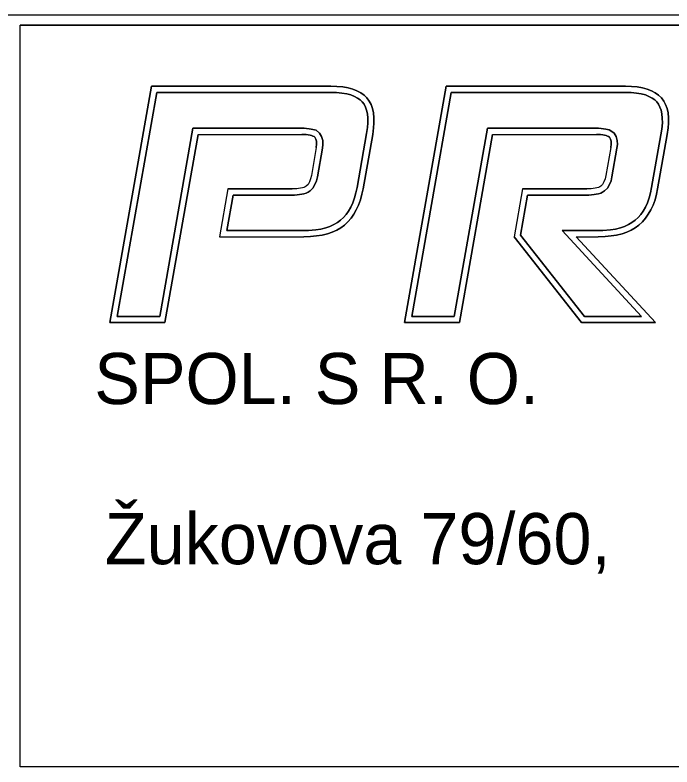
# Model space of a CAD drawing. Extents: x 448 to 763, y 27 to 171.
# Drawn here: x 731.72 to 743.92, y 48.52 to 62.49 of the extents above; entities that cross this region are included whole.
import ezdxf

# ---------------------------------------------------------------- set-up
doc = ezdxf.new("R2010")
doc.units = 0
doc.layers.add('000_rozpiska', color=7, linetype='Continuous')

msp = doc.modelspace()

# ---------------------------------------------------------------- linework, layer by layer
at = {"layer": '000_rozpiska'}
for p, q in [((758.888, 62.487), (672.438, 62.487)), ((758.888, 62.487), (672.438, 62.487)), ((758.888, 62.297), (731.813, 62.297)), ((731.813, 48.521), (731.813, 62.297)), ((733.48, 56.774), (734.254, 61.165)), ((734.253, 61.165), (737.585, 61.165)), ((738.951, 56.774), (739.725, 61.165)), ((739.724, 61.165), (743.056, 61.165)), ((735.118, 60.27), (734.502, 56.774)), ((735.118, 60.27), (737.047, 60.27)), ((738.361, 60.27), (738.183, 59.257)), ((740.589, 60.27), (739.973, 56.774)), ((740.589, 60.27), (742.518, 60.27)), ((743.832, 60.27), (743.654, 59.257)), ((737.314, 60.027), (737.222, 59.507)), ((742.785, 60.027), (742.693, 59.507)), ((735.672, 59.257), (735.516, 58.37)), ((735.672, 59.257), (736.868, 59.257)), ((741.143, 59.257), (740.987, 58.37)), ((741.143, 59.257), (742.339, 59.257)), ((735.516, 58.37), (737.081, 58.37)), ((742.239, 56.774), (740.987, 58.37)), ((742.14, 58.37), (742.551, 58.37)), ((743.615, 56.774), (742.14, 58.37)), ((734.502, 56.774), (733.48, 56.774)), ((739.973, 56.774), (738.951, 56.774)), ((743.615, 56.774), (742.239, 56.774)), ((760.123, 48.521), (731.813, 48.521))]:
    msp.add_line(p, q, dxfattribs=at)
for points in [[(731.813, 48.521), (731.813, 62.297), (758.888, 62.297)], [(760.123, 61.062), (760.123, 48.521), (731.813, 48.521)], [(737.991, 61.111), (737.903, 61.135), (737.804, 61.152), (737.697, 61.162), (737.585, 61.165), (734.254, 61.165), (733.48, 56.774), (734.502, 56.774), (735.118, 60.27), (737.047, 60.27), (737.082, 60.269), (737.124, 60.267), (737.163, 60.263), (737.197, 60.257), (737.226, 60.25), (737.251, 60.24), (737.271, 60.229), (737.287, 60.216), (737.308, 60.184), (737.319, 60.142), (737.32, 60.087), (737.314, 60.027), (737.222, 59.507), (737.207, 59.444), (737.186, 59.387), (737.16, 59.342), (737.127, 59.309), (737.107, 59.297), (737.084, 59.286), (737.055, 59.277), (737.023, 59.269), (736.986, 59.264), (736.949, 59.26), (736.904, 59.258), (736.868, 59.257), (735.672, 59.257), (735.516, 58.37), (737.081, 58.37), (737.207, 58.373), (737.32, 58.384), (737.421, 58.4), (737.524, 58.426), (737.609, 58.455), (737.694, 58.494), (737.768, 58.537), (737.836, 58.587), (737.902, 58.645), (737.959, 58.712), (738.01, 58.786), (738.057, 58.867), (738.098, 58.957), (738.134, 59.057), (738.162, 59.16), (738.183, 59.257), (738.361, 60.27), (738.378, 60.389), (738.385, 60.481), (738.383, 60.58), (738.376, 60.669), (738.357, 60.751), (738.331, 60.823), (738.297, 60.89), (738.253, 60.948), (738.201, 60.999), (738.14, 61.043), (738.069, 61.08), (737.991, 61.111)], [(734.349, 61.051), (737.581, 61.051), (737.69, 61.048), (737.789, 61.039), (737.878, 61.023), (737.956, 61.002), (738.022, 60.976), (738.08, 60.946), (738.128, 60.911), (738.167, 60.873), (738.2, 60.829), (738.226, 60.778), (738.247, 60.72), (738.263, 60.651), (738.269, 60.574), (738.271, 60.484), (738.265, 60.401), (738.249, 60.288), (738.071, 59.281), (738.051, 59.187), (738.025, 59.092), (737.992, 59), (737.955, 58.92), (737.914, 58.847), (737.868, 58.782), (737.82, 58.725), (737.764, 58.675), (737.706, 58.633), (737.642, 58.595), (737.566, 58.561), (737.492, 58.535), (737.398, 58.512), (737.305, 58.497), (737.168, 58.484), (735.652, 58.484), (735.768, 59.143), (736.87, 59.143), (736.907, 59.144), (736.957, 59.146), (737.001, 59.151), (737.044, 59.157), (737.085, 59.167), (737.126, 59.18), (737.161, 59.196), (737.199, 59.219), (737.251, 59.272), (737.289, 59.337), (737.317, 59.41), (737.334, 59.484), (737.427, 60.014), (737.435, 60.083), (737.432, 60.158), (737.413, 60.231), (737.373, 60.293), (737.309, 60.346), (737.22, 60.369), (737.179, 60.376), (737.133, 60.381), (737.086, 60.383), (737.05, 60.384), (735.022, 60.384), (734.406, 56.888), (733.616, 56.888), (734.349, 61.051)], [(738.263, 60.651), (738.247, 60.72), (738.226, 60.778), (738.2, 60.829), (738.167, 60.873), (738.128, 60.911), (738.08, 60.946), (738.022, 60.976), (737.956, 61.002), (737.878, 61.023), (737.789, 61.039), (737.69, 61.048), (737.581, 61.051), (734.349, 61.051), (733.616, 56.888), (734.406, 56.888), (735.022, 60.384), (737.05, 60.384), (737.086, 60.383), (737.133, 60.381), (737.179, 60.376), (737.22, 60.369), (737.309, 60.346), (737.373, 60.293), (737.413, 60.231), (737.432, 60.158), (737.435, 60.083), (737.427, 60.014), (737.334, 59.484), (737.317, 59.41), (737.289, 59.337), (737.251, 59.272), (737.199, 59.219), (737.161, 59.196), (737.126, 59.18), (737.085, 59.167), (737.044, 59.157), (737.001, 59.151), (736.957, 59.146), (736.907, 59.144), (736.87, 59.143), (735.768, 59.143), (735.652, 58.484), (737.168, 58.484), (737.305, 58.497), (737.398, 58.512), (737.492, 58.535), (737.566, 58.561), (737.642, 58.595), (737.706, 58.633), (737.764, 58.675), (737.82, 58.725), (737.868, 58.782), (737.914, 58.847), (737.955, 58.92), (737.992, 59), (738.025, 59.092), (738.051, 59.187), (738.071, 59.281), (738.249, 60.288), (738.265, 60.401), (738.271, 60.484), (738.269, 60.574), (738.263, 60.651)], [(735.022, 60.384), (734.406, 56.888), (733.616, 56.888), (734.349, 61.051), (737.581, 61.051), (737.69, 61.048), (737.789, 61.039), (737.878, 61.023), (737.956, 61.002), (738.022, 60.976), (738.08, 60.946), (738.128, 60.911), (738.167, 60.873), (738.2, 60.829), (738.226, 60.778), (738.247, 60.72), (738.263, 60.651), (738.269, 60.574), (738.271, 60.484), (738.265, 60.401), (738.249, 60.288), (738.071, 59.281), (738.051, 59.187), (738.025, 59.092), (737.992, 59), (737.955, 58.92), (737.914, 58.847), (737.868, 58.782), (737.82, 58.725), (737.764, 58.675), (737.706, 58.633), (737.642, 58.595), (737.566, 58.561), (737.492, 58.535), (737.398, 58.512), (737.305, 58.497), (737.168, 58.484), (735.652, 58.484), (735.768, 59.143), (736.87, 59.143), (736.907, 59.144), (736.957, 59.146), (737.001, 59.151), (737.044, 59.157), (737.085, 59.167), (737.126, 59.18), (737.161, 59.196), (737.199, 59.219), (737.251, 59.272), (737.289, 59.337), (737.317, 59.41), (737.334, 59.484), (737.427, 60.014), (737.435, 60.083), (737.432, 60.158), (737.413, 60.231), (737.373, 60.293), (737.309, 60.346), (737.22, 60.369), (737.179, 60.376), (737.133, 60.381), (737.086, 60.383), (737.05, 60.384), (735.022, 60.384)], [(737.585, 61.165), (737.697, 61.162), (737.804, 61.152), (737.903, 61.135), (737.991, 61.111), (738.069, 61.08), (738.14, 61.043), (738.201, 60.999), (738.253, 60.948), (738.297, 60.89), (738.331, 60.823), (738.357, 60.751), (738.376, 60.669), (738.383, 60.58), (738.385, 60.481), (738.378, 60.389), (738.361, 60.27)], [(743.849, 60.389), (743.856, 60.481), (743.854, 60.58), (743.847, 60.669), (743.828, 60.751), (743.802, 60.823), (743.768, 60.89), (743.724, 60.948), (743.672, 60.999), (743.611, 61.043), (743.54, 61.08), (743.462, 61.111), (743.374, 61.135), (743.275, 61.152), (743.168, 61.162), (743.056, 61.165), (739.725, 61.165), (738.951, 56.774), (739.973, 56.774), (740.589, 60.27), (742.518, 60.27), (742.553, 60.269), (742.595, 60.267), (742.634, 60.263), (742.668, 60.257), (742.697, 60.25), (742.722, 60.24), (742.742, 60.229), (742.758, 60.216), (742.779, 60.184), (742.79, 60.142), (742.791, 60.087), (742.785, 60.027), (742.693, 59.507), (742.678, 59.444), (742.657, 59.387), (742.631, 59.342), (742.598, 59.309), (742.578, 59.297), (742.555, 59.286), (742.526, 59.277), (742.494, 59.269), (742.457, 59.264), (742.42, 59.26), (742.375, 59.258), (742.339, 59.257), (741.143, 59.257), (740.987, 58.37), (742.239, 56.774), (743.615, 56.774), (742.14, 58.37), (742.551, 58.37), (742.678, 58.373), (742.791, 58.384), (742.892, 58.4), (742.995, 58.426), (743.08, 58.455), (743.165, 58.494), (743.239, 58.537), (743.307, 58.587), (743.373, 58.645), (743.43, 58.712), (743.481, 58.786), (743.528, 58.867), (743.569, 58.957), (743.605, 59.057), (743.633, 59.16), (743.654, 59.257), (743.832, 60.27), (743.849, 60.389)], [(740.493, 60.384), (739.877, 56.888), (739.087, 56.888), (739.82, 61.051), (743.052, 61.051), (743.161, 61.048), (743.26, 61.039), (743.349, 61.023), (743.426, 61.002), (743.493, 60.976), (743.551, 60.946), (743.599, 60.911), (743.638, 60.873), (743.671, 60.829), (743.697, 60.778), (743.718, 60.72), (743.734, 60.651), (743.74, 60.574), (743.742, 60.484), (743.733, 60.365), (743.542, 59.281), (743.522, 59.187), (743.496, 59.092), (743.463, 59), (743.426, 58.92), (743.385, 58.847), (743.339, 58.782), (743.291, 58.725), (743.235, 58.675), (743.177, 58.633), (743.113, 58.595), (743.037, 58.561), (742.963, 58.535), (742.869, 58.512), (742.776, 58.497), (742.639, 58.484), (741.88, 58.484), (743.355, 56.888), (742.295, 56.888), (741.108, 58.4), (741.239, 59.143), (742.341, 59.143), (742.378, 59.144), (742.428, 59.146), (742.472, 59.151), (742.515, 59.157), (742.556, 59.167), (742.597, 59.18), (742.632, 59.196), (742.67, 59.219), (742.722, 59.272), (742.76, 59.337), (742.788, 59.41), (742.805, 59.484), (742.898, 60.014), (742.906, 60.083), (742.903, 60.158), (742.884, 60.231), (742.844, 60.293), (742.806, 60.324), (742.754, 60.353), (742.691, 60.369), (742.65, 60.376), (742.604, 60.381), (742.557, 60.383), (742.521, 60.384), (740.493, 60.384)], [(743.697, 60.778), (743.671, 60.829), (743.638, 60.873), (743.599, 60.911), (743.551, 60.946), (743.493, 60.976), (743.426, 61.002), (743.349, 61.023), (743.26, 61.039), (743.161, 61.048), (743.052, 61.051), (739.82, 61.051), (739.087, 56.888), (739.877, 56.888), (740.493, 60.384), (742.521, 60.384), (742.557, 60.383), (742.604, 60.381), (742.65, 60.376), (742.691, 60.369), (742.754, 60.353), (742.806, 60.324), (742.844, 60.293), (742.884, 60.231), (742.903, 60.158), (742.906, 60.083), (742.898, 60.014), (742.805, 59.484), (742.788, 59.41), (742.76, 59.337), (742.722, 59.272), (742.67, 59.219), (742.632, 59.196), (742.597, 59.18), (742.556, 59.167), (742.515, 59.157), (742.472, 59.151), (742.428, 59.146), (742.378, 59.144), (742.341, 59.143), (741.239, 59.143), (741.108, 58.4), (742.295, 56.888), (743.355, 56.888), (741.88, 58.484), (742.639, 58.484), (742.776, 58.497), (742.869, 58.512), (742.963, 58.535), (743.037, 58.561), (743.113, 58.595), (743.177, 58.633), (743.235, 58.675), (743.291, 58.725), (743.339, 58.782), (743.385, 58.847), (743.426, 58.92), (743.463, 59), (743.496, 59.092), (743.522, 59.187), (743.542, 59.281), (743.733, 60.365), (743.742, 60.484), (743.74, 60.574), (743.734, 60.651), (743.718, 60.72), (743.697, 60.778)], [(740.493, 60.384), (739.877, 56.888), (739.087, 56.888), (739.82, 61.051), (743.052, 61.051), (743.161, 61.048), (743.26, 61.039), (743.349, 61.023), (743.426, 61.002), (743.493, 60.976), (743.551, 60.946), (743.599, 60.911), (743.638, 60.873), (743.671, 60.829), (743.697, 60.778), (743.718, 60.72), (743.734, 60.651), (743.74, 60.574), (743.742, 60.484), (743.733, 60.365), (743.542, 59.281), (743.522, 59.187), (743.496, 59.092), (743.463, 59), (743.426, 58.92), (743.385, 58.847), (743.339, 58.782), (743.291, 58.725), (743.235, 58.675), (743.177, 58.633), (743.113, 58.595), (743.037, 58.561), (742.963, 58.535), (742.869, 58.512), (742.776, 58.497), (742.639, 58.484), (741.88, 58.484), (743.355, 56.888), (742.295, 56.888), (741.108, 58.4), (741.239, 59.143), (742.341, 59.143), (742.378, 59.144), (742.428, 59.146), (742.472, 59.151), (742.515, 59.157), (742.556, 59.167), (742.597, 59.18), (742.632, 59.196), (742.67, 59.219), (742.722, 59.272), (742.76, 59.337), (742.788, 59.41), (742.805, 59.484), (742.898, 60.014), (742.906, 60.083), (742.903, 60.158), (742.884, 60.231), (742.844, 60.293), (742.806, 60.324), (742.754, 60.353), (742.691, 60.369), (742.65, 60.376), (742.604, 60.381), (742.557, 60.383), (742.521, 60.384), (740.493, 60.384)], [(743.056, 61.165), (743.168, 61.162), (743.275, 61.152), (743.374, 61.135), (743.462, 61.111), (743.54, 61.08), (743.611, 61.043), (743.672, 60.999), (743.724, 60.948), (743.768, 60.89), (743.802, 60.823), (743.828, 60.751), (743.847, 60.669), (743.854, 60.58), (743.856, 60.481), (743.849, 60.389), (743.832, 60.27)], [(737.226, 60.25), (737.197, 60.257), (737.163, 60.263), (737.124, 60.267), (737.082, 60.269), (737.047, 60.27)], [(737.314, 60.027), (737.32, 60.087), (737.319, 60.142), (737.308, 60.184), (737.287, 60.216), (737.271, 60.229), (737.251, 60.24), (737.226, 60.25)], [(742.697, 60.25), (742.668, 60.257), (742.634, 60.263), (742.595, 60.267), (742.553, 60.269), (742.518, 60.27)], [(742.785, 60.027), (742.791, 60.087), (742.79, 60.142), (742.779, 60.184), (742.758, 60.216), (742.742, 60.229), (742.722, 60.24), (742.697, 60.25)], [(737.222, 59.507), (737.207, 59.444), (737.186, 59.387), (737.16, 59.342), (737.127, 59.309), (737.107, 59.297), (737.084, 59.286), (737.055, 59.277), (737.023, 59.269), (736.986, 59.264), (736.949, 59.26), (736.904, 59.258), (736.868, 59.257)], [(742.693, 59.507), (742.678, 59.444), (742.657, 59.387), (742.631, 59.342), (742.598, 59.309), (742.578, 59.297), (742.555, 59.286), (742.526, 59.277), (742.494, 59.269), (742.457, 59.264), (742.42, 59.26), (742.375, 59.258), (742.339, 59.257)], [(738.183, 59.257), (738.162, 59.16), (738.134, 59.057), (738.098, 58.957), (738.057, 58.867), (738.01, 58.786), (737.959, 58.712), (737.902, 58.645), (737.836, 58.587), (737.768, 58.537), (737.694, 58.494), (737.609, 58.455), (737.524, 58.426), (737.421, 58.4), (737.32, 58.384), (737.207, 58.373), (737.081, 58.37)], [(743.654, 59.257), (743.633, 59.16), (743.605, 59.057), (743.569, 58.957), (743.528, 58.867), (743.481, 58.786), (743.43, 58.712), (743.373, 58.645), (743.307, 58.587), (743.239, 58.537), (743.165, 58.494), (743.08, 58.455), (742.995, 58.426), (742.892, 58.4), (742.791, 58.384), (742.678, 58.373), (742.551, 58.37)]]:
    msp.add_lwpolyline(points, dxfattribs=at)

# ---------------------------------------------------------------- texts
for s, p in [('SPOL. S R. O.', (733.19, 55.261)), ('Žukovova 79/60, ', (733.386, 52.287))]:
    msp.add_text(s, height=0.95, dxfattribs=at).set_placement(p)

doc.saveas('drawing.dxf')
